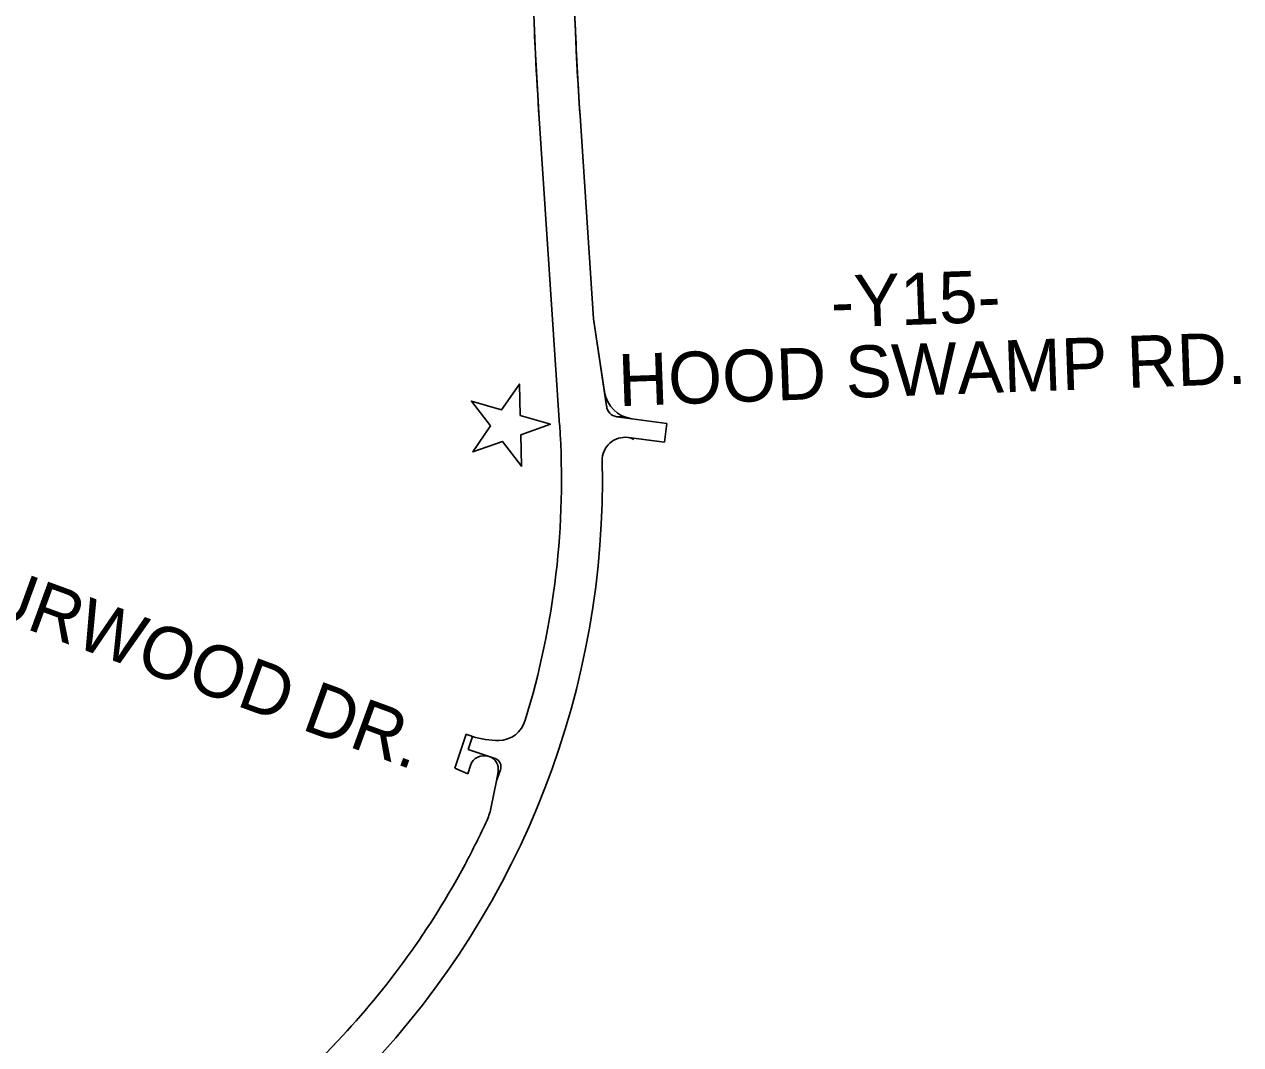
# Model space of a CAD drawing. Extents: x 2312641 to 2338852, y 590461 to 618614.
# Drawn here: x 2327470 to 2329579, y 603449 to 605218 of the extents above; entities that cross this region are included whole.
import ezdxf

# ---------------------------------------------------------------- set-up
doc = ezdxf.new("R2010")
doc.units = 0
for name, color, linetype in [('Default Symbol CELL', 7, 'Continuous'), ('Exist Property Monument CELL', 7, 'Continuous'), ('Exist Structure Minor Pipes RCP 15 Inch Text', 7, 'Continuous'), ('Exist Structure Minor Storm Sewer Manhole Cogo Elevation', 7, 'Continuous')]:
    doc.layers.add(name, color=color, linetype=linetype)

msp = doc.modelspace()

# ---------------------------------------------------------------- linework, layer by layer
at = {"layer": 'Default Symbol CELL'}
for p, q in [((2328398, 604523.5), (2328362.5, 605054.8)), ((2328456.9, 604707.7), (2328433.4, 605059.5)), ((2328479.5, 604556.5), (2328456.9, 604707.7)), ((2328496.9, 604538), (2328584.1, 604526.4)), ((2328579.7, 604493.7), (2328584.1, 604526.4)), ((2328517.1, 604502), (2328579.7, 604493.7)), ((2328246.8, 603983.8), (2328239.1, 603961.1)), ((2328285.9, 603945.4), (2328239.1, 603961.1)), ((2327504.8, 602919.8), (2328013.2, 603456))]:
    msp.add_line(p, q, dxfattribs=at)
for centre, radius, start, end in [((2334374.6, 605456.5), 5954.5, 177.28089, 183.82261), ((2334374.6, 605456.5), 6025.5, 181.71156, 183.82261), ((2328499.5, 604557.8), 20, 183.8226, 262.4373), ((2326986.7, 604429.2), 1414.5, 342.8477, 3.8226), ((2328500.1, 604562.8), 25, 262.4373, 285.5112), ((2328511.8, 604462.3), 40, 82.4373, 181.243), ((2328513.8, 604477.2), 25, 59.3634, 82.4373), ((2326986.7, 604429.2), 1485.5, 316.5265, 1.243), ((2328291.9, 604024.6), 48, 270.4863, 344.8807), ((2328291.2, 604116.6), 140, 251.5098, 270.4863), ((2328281.2, 603931.2), 15, 339.4907, 71.5098), ((2326986.7, 604429.2), 1414.5, 316.5265, 331.8504)]:
    msp.add_arc(centre, radius, start, end, dxfattribs=at)
at = {"layer": 'Exist Property Monument CELL'}
for p, q in [((2328362.5, 605054.8), (2328398, 604523.5)), ((2328456.9, 604707.7), (2328433.4, 605059.5)), ((2328475.9, 604580.9), (2328456.9, 604707.7)), ((2328584.1, 604526.4), (2328523, 604534.5)), ((2328579.7, 604493.7), (2328584.1, 604526.4)), ((2328517.1, 604502), (2328552.8, 604497.3)), ((2328236.1, 603987.4), (2328216.5, 603928.8)), ((2328246.8, 603983.8), (2328236.1, 603987.4)), ((2328216.5, 603928.8), (2328238.5, 603919)), ((2328238.5, 603919), (2328243.3, 603933.3)), ((2328274.9, 603949.1), (2328274.9, 603949.1)), ((2328274.9, 603949.1), (2328275.9, 603948.8)), ((2328291.2, 603922.6), (2328288.2, 603907)), ((2328295.3, 603926.2), (2328295.3, 603926.2)), ((2328288.2, 603907), (2328279.4, 603861.6)), ((2328013.2, 603456), (2328006.9, 603449.4))]:
    msp.add_line(p, q, dxfattribs=at)
for points in [[(2328552.8, 604497.3), (2328552.8, 604497.3), (2328579.7, 604493.7)], [(2328288.2, 603907), (2328295.2, 603925.9), (2328295.3, 603926.2)], [(2328295.3, 603926.2), (2328295.2, 603925.9), (2328288.2, 603907)]]:
    msp.add_lwpolyline(points, dxfattribs=at)
for centre, radius, start, end in [((2334374.6, 605456.5), 5954.5, 182.08511, 183.82261), ((2334374.6, 605456.5), 6025.5, 182.26677, 183.82261), ((2328530.3, 604589), 55, 188.511, 262.4373), ((2326986.7, 604429.2), 1414.5, 342.8477, 3.8226), ((2328511.8, 604462.3), 40, 82.4373, 181.243), ((2328534.3, 604358.5), 140, 82.43736222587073, 82.43742515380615), ((2326986.7, 604429.2), 1485.5, 316.5265, 1.243), ((2328291.9, 604024.6), 48, 270.4863, 344.8807), ((2328291.2, 604116.6), 140, 251.5098, 270.4863), ((2328267, 603925.4), 25, 71.5101, 161.5098), ((2328268.6, 603927), 23, 349.0617, 71.5098), ((2328181.2, 603880.5), 100, 335.3276, 349.0617), ((2326986.7, 604429.2), 1414.5, 331.8504, 335.3276), ((2326986.7, 604429.2), 1414.5, 316.5265, 331.8504)]:
    msp.add_arc(centre, radius, start, end, dxfattribs=at)
at = {"layer": 'Exist Structure Minor Storm Sewer Manhole Cogo Elevation'}
msp.add_lwpolyline([(2328278.3, 604521.9), (2328247.6, 604477), (2328298.8, 604495.2), (2328332.1, 604452), (2328330.6, 604506.5), (2328381.9, 604524.8), (2328329.7, 604540.2), (2328328.2, 604594.6), (2328297.4, 604549.7), (2328245.1, 604565.1), (2328278.3, 604521.9)], dxfattribs=at)

# ---------------------------------------------------------------- texts
at = {"layer": 'Exist Structure Minor Pipes RCP 15 Inch Text'}
for s, rotation, p in [('-Y15-', 2.0577, (2328869.8, 604692.2)), ('HOOD SWAMP RD.', 2.0577, (2328500.8, 604556.1)), ('-Y14- DURWOOD DR.', 339.9468, (2326999.7, 604342.8))]:
    msp.add_text(s, height=90, rotation=rotation, dxfattribs=at).set_placement(p)

doc.saveas('drawing.dxf')
